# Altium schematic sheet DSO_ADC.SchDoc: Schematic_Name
size A4; CompanyName: University of Melbourne; Engineer: Your Name Here; DocumentNumber: 1; Revision: 0.1; SheetNumber: 1; SheetTotal: 1; Title_Project: Project_Title; StudentNo: Student No.
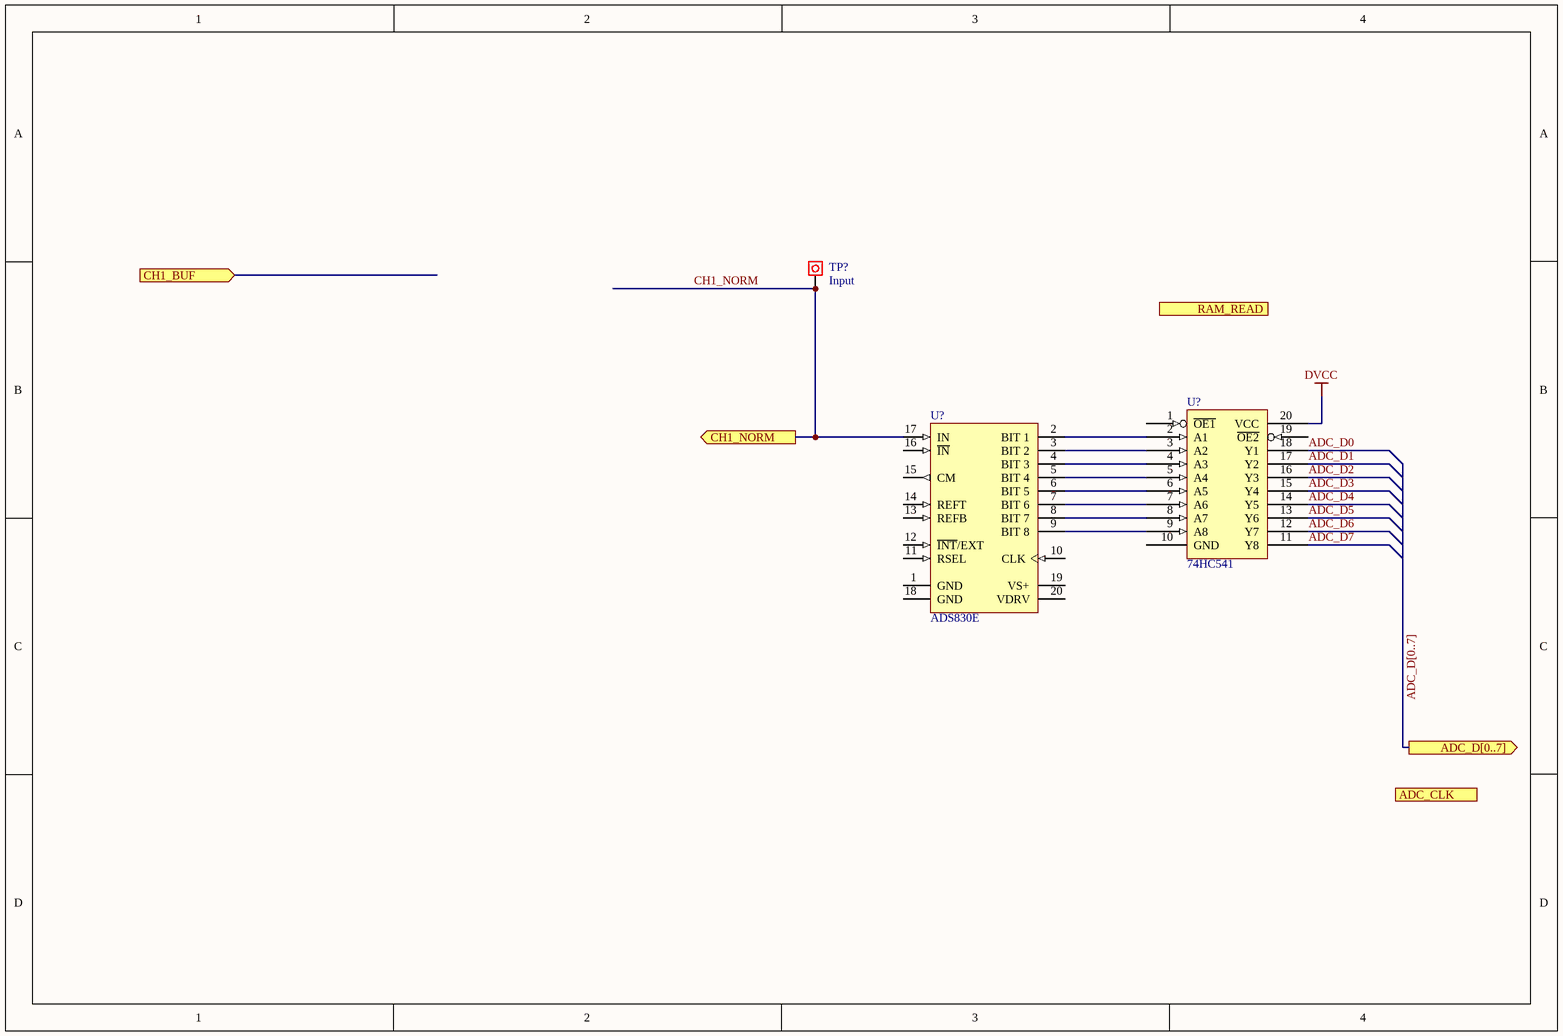
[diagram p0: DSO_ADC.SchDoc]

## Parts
(Parts that share a designator on the sheet are numbered #1, #2 ... from top to bottom, then left to right.)
TP?  INPUT  [Testpoin]
U?#1  ADS830E  [TI-DBQ20_L]
U?#2  74HC541  [SOT163-1_N]

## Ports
ADC_CLK (in), ADC_D[0..7] (out), CH1_BUF (in), CH1_NORM (out), RAM_READ (in)

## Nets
DVCC: U?#2.20(VCC)
ADC_D0: U?#2.18(Y1)
ADC_D1: U?#2.17(Y2)
ADC_D2: U?#2.16(Y3)
ADC_D3: U?#2.15(Y4)
ADC_D4: U?#2.14(Y5)
ADC_D5: U?#2.13(Y6)
ADC_D6: U?#2.12(Y7)
ADC_D7: U?#2.11(Y8)
CH1_NORM: TP?.1 U?#1.17(IN) ; port CH1_NORM
NetU?#1_2: U?#1.2(BIT_1) U?#2.2(A1)
NetU?#1_3: U?#1.3(BIT_2) U?#2.3(A2)
NetU?#1_4: U?#1.4(BIT_3) U?#2.4(A3)
NetU?#1_5: U?#1.5(BIT_4) U?#2.5(A4)
NetU?#1_6: U?#1.6(BIT_5) U?#2.6(A5)
NetU?#1_7: U?#1.7(BIT_6) U?#2.7(A6)
NetU?#1_8: U?#1.8(BIT_7) U?#2.8(A7)
NetU?#1_9: U?#1.9(BIT_8) U?#2.9(A8)

Not connected (* = marked no-connect by the designer): U?#1 1(GND) 10(CLK) 11(RSEL) 12(~{INT}/EXT) 13(REFB) 14(REFT) 15(CM) 16(~{IN}) 18(GND) 19(VS+) 20(VDRV); U?#2 1(~{OE1}) 10(GND) 19(~{OE2})

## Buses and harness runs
bus ADC_D[0..7] = port ADC_D[0..7]

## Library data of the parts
TP? = Test Point: Pad
U?#1 = ADS830E: 8-Bit, 60 MSPS ADC Single-Ended / Differential Input, Internal / External Reference and Programmble Input Range, -40 to 85 degC, 20-pin SOP (DBQ20), Green (RoHS & no Sb/Br); Reviewed by: RM - 2018/08/05
U?#2 = 74HC541: (ADV) Octal Buffer, Line Driver; Reviewed by: RM - 2018/08/05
